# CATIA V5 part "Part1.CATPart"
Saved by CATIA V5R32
Part number: Part1
Bounding box of the stored display mesh (mm): x -100 to 100, y -50 to 50, z -20 to 20
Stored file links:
  D:\PROJECTS\Project 2022\CATIA V5 6R 2022\Resources\Part Files\c16_catia_v5_6r2022_prt\Prismatic Joint-(Fig16-14)\Part1.CATPart
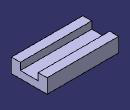
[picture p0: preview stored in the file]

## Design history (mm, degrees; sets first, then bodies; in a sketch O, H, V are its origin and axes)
Body1 (main body)
  Sketch1 on yz-plane, origin (0, 0, 0), H (0, 1, 0), V (0, 0, 1)
    line L1 (50, 20) -> (50, -20)
    line L2 (50, -20) -> (-50, -20)
    line L3 (-50, -20) -> (-50, 20)
    point P1 (50, 20)
    point P4 (-50, 20)
    point P5 (0, 8.2157)
    line L4 (25, 20) -> (25, 0)
    line L5 (25, 0) -> (-25, 0)
    line L6 (-25, 0) -> (-25, 20)
    line L7 (-25, 20) -> (-50, 20)
    point P10 (-50, 20)
    line L8 (25, 20) -> (50, 20)
    point P11 (50, 20)
    distance V L3 = 50
    distance L6 V = 25
    length L5 = 50
    distance L2 L5 = 20
    length L3 = 40
    vertical: L1 V, L3 V, L4 V, L6 V
    horizontal: L2 H, L5 H, L7 H, L8 H
    equidistance: L1 L3 O, L4 L6 P5
    coincidence: P4 P10, P11 L1, P11 P1, L7 L8, H L5
  Pad1: profile Sketch1, direction (1, 0, 0), length 100, mirrored extent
